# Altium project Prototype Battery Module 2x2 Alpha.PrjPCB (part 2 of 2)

## Sheet Host Comm.SchDoc: Host Communication
size B; Date: 12/18/2013; DrawnBy: David McCoy; Engineer: David McCoy (Cospan Design); DocumentNumber: 12; Revision: C; SheetNumber: 12; SheetTotal: 13
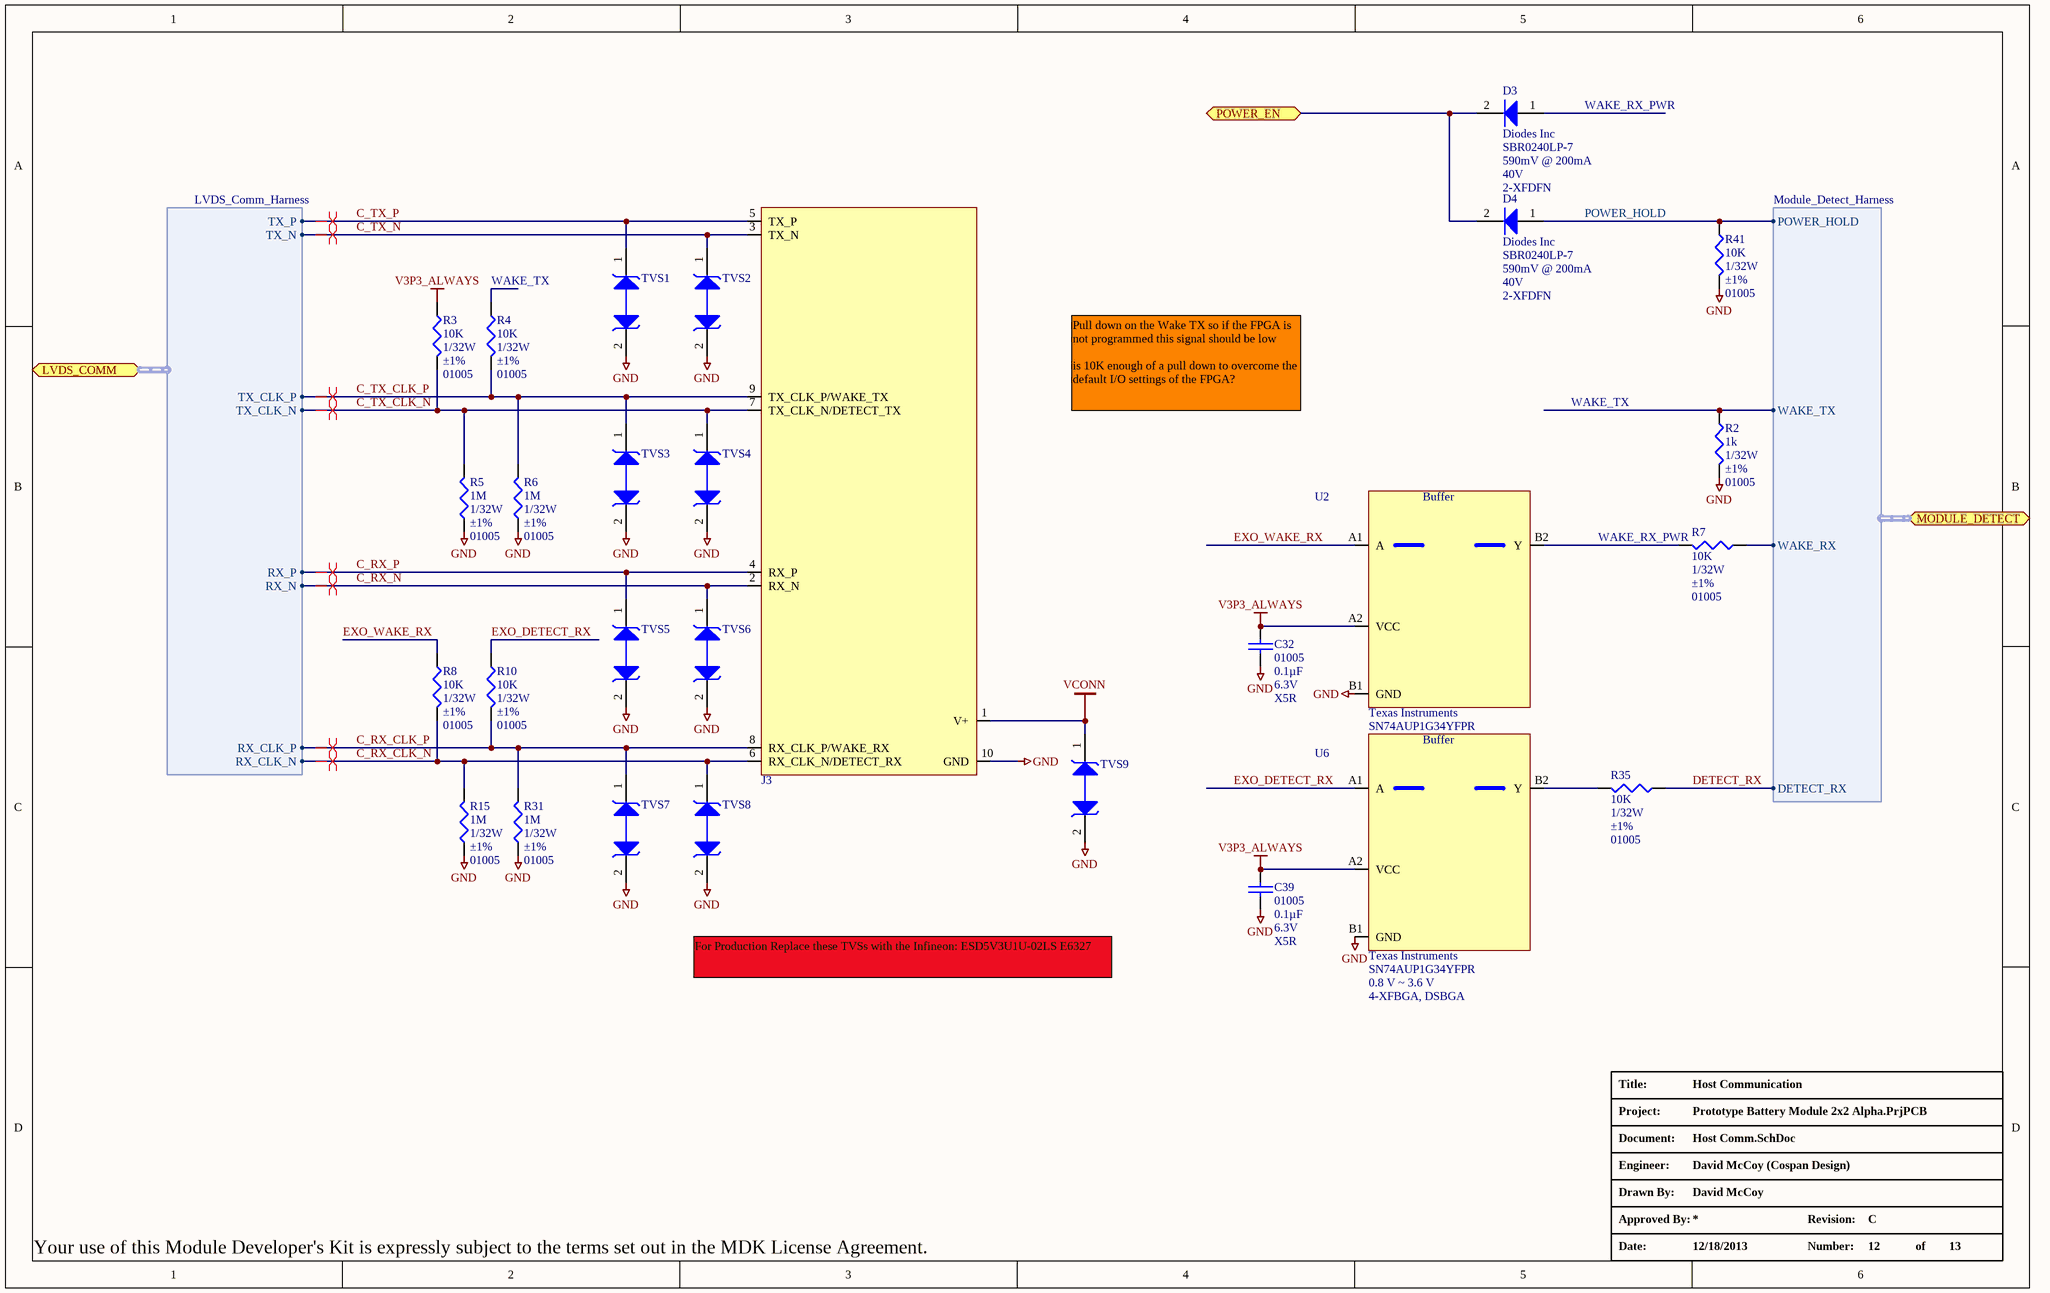
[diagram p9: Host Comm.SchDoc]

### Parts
C32  Package / Case: 01005  Capacitance: 0.1µF  Voltage - Rated: 6.3V  Temperature Coefficient: X5R  [C_01005]  (hidden comment: 0.1uF)
C39  Package / Case: 01005  Capacitance: 0.1µF  Voltage - Rated: 6.3V  Temperature Coefficient: X5R  [C_01005]  (hidden comment: 0.1uF)
D3  Manufacturer: Diodes Inc  Voltage - Forward (Vf) (Max) @ If: 590mV @ 200mA  Voltage - DC Reverse (Vr) (Max): 40V  [2-XFDFN]  (hidden comment: SBR0240LP-7)
D4  Manufacturer: Diodes Inc  Voltage - Forward (Vf) (Max) @ If: 590mV @ 200mA  Voltage - DC Reverse (Vr) (Max): 40V  [2-XFDFN]  (hidden comment: SBR0240LP-7)
J3  SPRING PIN  [10PIN SMD CONNECTOR]  (value not drawn)  (no BOM)
R2  Power (Watts): 1/32W  Tolerance: ±1%  Case: 01005  [R_01005]  (hidden comment: 1k)
R3  Power (Watts): 1/32W  Tolerance: ±1%  Case: 01005  [R_01005]  (hidden comment: 10K)
R4  Power (Watts): 1/32W  Tolerance: ±1%  Case: 01005  [R_01005]  (hidden comment: 10K)
R5  Resistance In Ohms: 1M  Power (Watts): 1/32W  Tolerance: ±1%  Case: 01005  [R_01005]  (hidden comment: 1M Ohms)
R6  Resistance In Ohms: 1M  Power (Watts): 1/32W  Tolerance: ±1%  Case: 01005  [R_01005]  (hidden comment: 1M Ohms)
R7  Power (Watts): 1/32W  Tolerance: ±1%  Case: 01005  [R_01005]  (hidden comment: 10K)
R8  Power (Watts): 1/32W  Tolerance: ±1%  Case: 01005  [R_01005]  (hidden comment: 10K)
R10  Power (Watts): 1/32W  Tolerance: ±1%  Case: 01005  [R_01005]  (hidden comment: 10K)
R15  Resistance In Ohms: 1M  Power (Watts): 1/32W  Tolerance: ±1%  Case: 01005  [R_01005]  (hidden comment: 1M Ohms)
R31  Resistance In Ohms: 1M  Power (Watts): 1/32W  Tolerance: ±1%  Case: 01005  [R_01005]  (hidden comment: 1M Ohms)
R35  Power (Watts): 1/32W  Tolerance: ±1%  Case: 01005  [R_01005]  (hidden comment: 10K)
R41  Power (Watts): 1/32W  Tolerance: ±1%  Case: 01005  [R_01005]  (hidden comment: 10K)
TVS1  TVS_ESDAVLC6-1BV2  [ST_MICRO_TVS]  (value not drawn)
TVS2  TVS_ESDAVLC6-1BV2  [ST_MICRO_TVS]  (value not drawn)
TVS3  TVS_ESDAVLC6-1BV2  [ST_MICRO_TVS]  (value not drawn)
TVS4  TVS_ESDAVLC6-1BV2  [ST_MICRO_TVS]  (value not drawn)
TVS5  TVS_ESDAVLC6-1BV2  [ST_MICRO_TVS]  (value not drawn)
TVS6  TVS_ESDAVLC6-1BV2  [ST_MICRO_TVS]  (value not drawn)
TVS7  TVS_ESDAVLC6-1BV2  [ST_MICRO_TVS]  (value not drawn)
TVS8  TVS_ESDAVLC6-1BV2  [ST_MICRO_TVS]  (value not drawn)
TVS9  TVS_ESDAVLC6-1BV2  [ST_MICRO_TVS]  (value not drawn)
U2  Manufacturer: Texas Instruments  Manufacturer Part Number: SN74AUP1G34YFPR  Voltage - Supply: 0.8 V ~ 3.6 V  Package / Case: 4-XFBGA, DSBGA  [DSBGA4_.4MM]  (hidden comment: Buffer)
U6  Manufacturer: Texas Instruments  Manufacturer Part Number: SN74AUP1G34YFPR  Voltage - Supply: 0.8 V ~ 3.6 V  Package / Case: 4-XFBGA, DSBGA  [DSBGA4_.4MM]  (hidden comment: Buffer)

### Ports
LVDS_COMM (harness LVDS_Comm_Harness), MODULE_DETECT (harness Module_Detect_Harness), POWER_EN

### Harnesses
Module_Detect_Harness: WAKE_TX, WAKE_RX, DETECT_RX, POWER_HOLD
LVDS_Comm_Harness: TX_P, TX_N, TX_CLK_P, TX_CLK_N, RX_P, RX_N, RX_CLK_P, RX_CLK_N

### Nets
GND: C32.1 C39.1 J3.10(GND) R2.1 R5.2 R6.2 R15.2 R31.2 R41.1 TVS1.2 TVS2.2 TVS3.2 TVS4.2 TVS5.2 TVS6.2 TVS7.2 TVS8.2 TVS9.2 U2.B1(GND) U6.B1(GND)
V3P3_ALWAYS: C32.2 C39.2 R3.2 U2.A2(VCC) U6.A2(VCC)
VCONN: J3.1(V+) TVS9.1
C_RX_CLK_N: J3.6(RX_CLK_N/DETECT_RX) R8.1 R15.1 TVS8.1 ; port LVDS_COMM.RX_CLK_N
C_RX_CLK_P: J3.8(RX_CLK_P/WAKE_RX) R10.1 R31.1 TVS7.1 ; port LVDS_COMM.RX_CLK_P
C_RX_N: J3.2(RX_N) TVS6.1 ; port LVDS_COMM.RX_N
C_RX_P: J3.4(RX_P) TVS5.1 ; port LVDS_COMM.RX_P
C_TX_CLK_N: J3.7(TX_CLK_N/DETECT_TX) R3.1 R5.1 TVS4.1 ; port LVDS_COMM.TX_CLK_N
C_TX_CLK_P: J3.9(TX_CLK_P/WAKE_TX) R4.1 R6.1 TVS3.1 ; port LVDS_COMM.TX_CLK_P
C_TX_N: J3.3(TX_N) TVS2.1 ; port LVDS_COMM.TX_N
C_TX_P: J3.5(TX_P) TVS1.1 ; port LVDS_COMM.TX_P
DETECT_RX: R35.2 ; port MODULE_DETECT.DETECT_RX
EXO_DETECT_RX: R10.2 U6.A1(A)
EXO_WAKE_RX: R8.2 U2.A1(A)
POWER_EN: D3.2(K) D4.2(K) ; port POWER_EN
POWER_HOLD: D4.1(A) R41.2 ; port MODULE_DETECT.POWER_HOLD
WAKE_RX: R7.2 ; port MODULE_DETECT.WAKE_RX
WAKE_RX_PWR: D3.1(A) R7.1 U2.B2(Y)
WAKE_TX: R2.2 R4.2 ; port MODULE_DETECT.WAKE_TX
NetR35_1: R35.1 U6.B2(Y)

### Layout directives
differential pair: C_RX_CLK_N, C_RX_CLK_P, C_RX_N, C_RX_P, C_TX_CLK_N, C_TX_CLK_P, C_TX_N, C_TX_P

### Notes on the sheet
- Pull down on the Wake TX so if the FPGA is not programmed this signal should be low
  is 10K enough of a pull down to overcome the default I/O settings of the FPGA?
- For Production Replace these TVSs with the Infineon: ESD5V3U1U-02LS E6327

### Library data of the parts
C32 C39 = C_01005_0.1uF: CAP CER 0.1UF 6.3V 20% X5R 01005; Manufacturer: TDK Corporation; Manufacturer Part Number: C0402X5R0J104M020BC
D3 D4 = D_SBR0240LP-7: DIODE SUP BARRIER 40V 0.25A 2DFN; Diode Type: Super Barrier; Current - Average Rectified (Io): 250mA; Speed: Fast Recovery =< 500ns, > 200mA (Io); Current - Reverse Leakage @ Vr: 10µA @ 40V; Thermal Resistance: 270°C/W Ja
J3 = J_TONKA_MODULE_CONNECTOR
R2 = R_01005_1k: RES 1K OHM 1/32W 1% 01005 SM; Manufacturer: Panasonic Electronic Components; Manufacturer Part Number: ERJ-XGNF1001Y; Temperature Coefficient: ±200ppm/°C
R3 R4 R7 R8 R10 R35 R41 = R_01005_10K: RES 10K OHM 1/32W 1% 01005; Manufacturer: Samsung Electro-Mechanics America, Inc; Manufacturer Part Number: RC0402F103CS; Temperature Coefficient: ±250ppm/°C
R5 R6 R15 R31 = R_01005_1M: RES 1M OHM 1/32W 1% 01005 SMD; Manufacturer: Yageo; Manufacturer Part Number: RC0100FR-071ML; Temperature Coefficient: ±250ppm/°C
TVS1-TVS9 = TVS_ESDAVLC6-1BV2: Single Line Bi Trans 8pF; Manufacturer: STMicroelectronics; Breakdown Voltage: 6 V; Capacitance: 7.5 pF; Clamping Voltage: 18 V; Channels: 1 Channel; Peak Pulse Power Dissipation: 45 W; Polarity: Bidirectional; Product Status: New Product
U2 U6 = U_SN74AUP1G34YFPR: IC BUFFER GATE SGL 4-DSBGA; Logic Type: Buffer/Line Driver, Non-Inverting; Number of Elements: 1; Current - Output High, Low: 4mA, 4mA

## Sheet Charger.SchDoc: Charger
size B; Date: 12/17/2013; DrawnBy: Ara Knaian; Engineer: Ara Knaian; DocumentNumber: 5; Revision: C; SheetNumber: 5; SheetTotal: 13
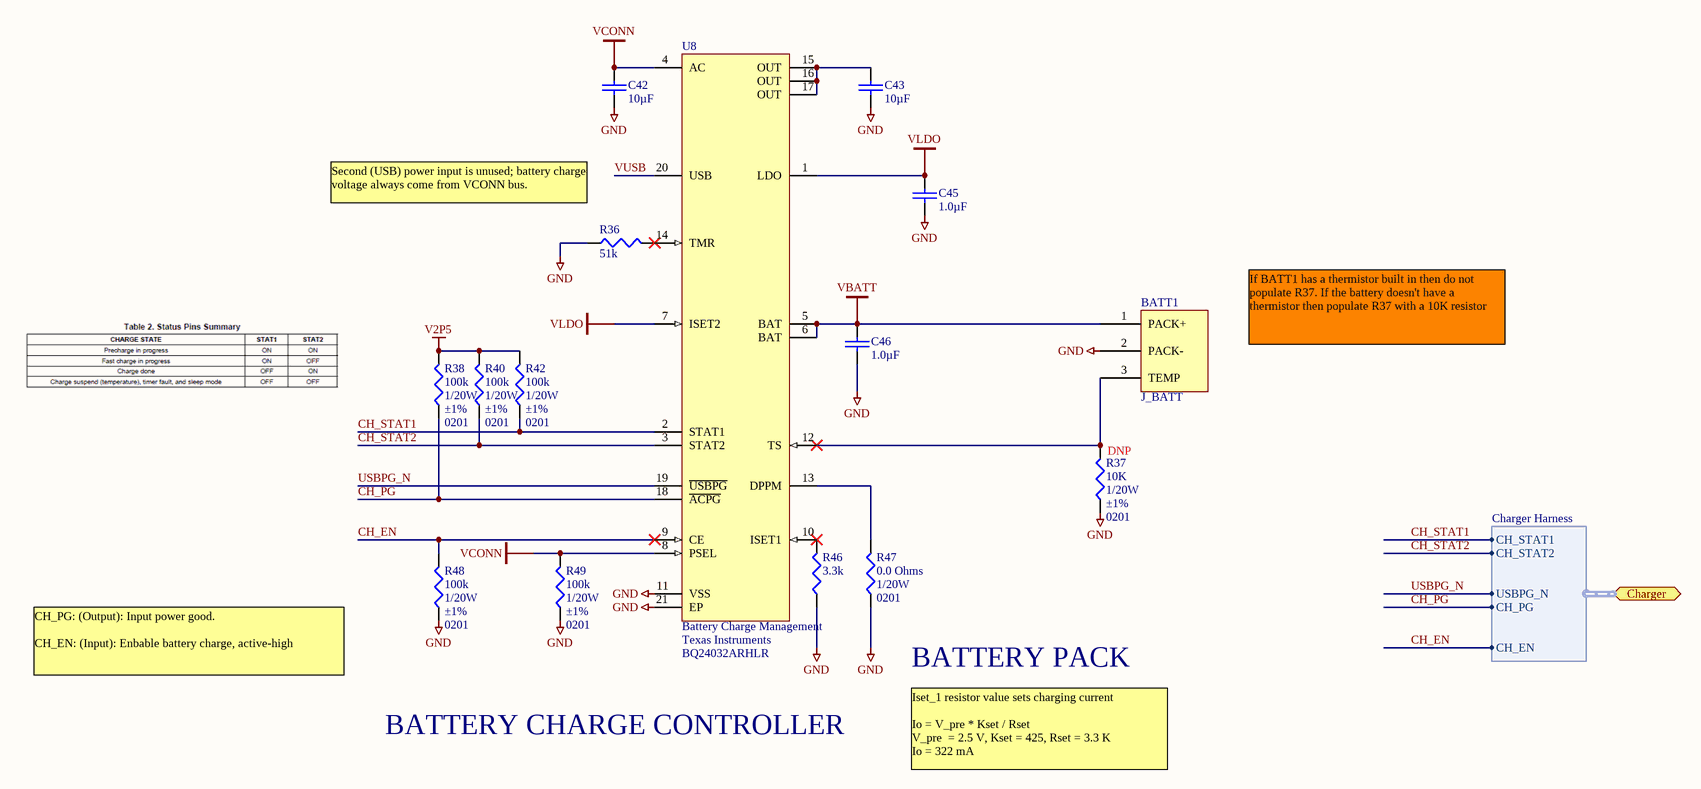
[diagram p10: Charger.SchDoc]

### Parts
BATT1  J_BATT  [1X3_PADS]  (no BOM)
C42  Capacitance: 10µF  [C_0402]  (hidden comment: C_0402_10uF)
C43  Capacitance: 10µF  [C_0402]  (hidden comment: C_0402_10uF)
C45  Capacitance: 1.0µF  [CAPC0201]  (hidden comment: 1uF)
C46  Capacitance: 1.0µF  [CAPC0201]  (hidden comment: 1uF)
R36  51K  [R_0201]
R37  Power (Watts): 1/20W  Tolerance: ±1%  Case: 0201  [R0201]  (hidden comment: 10K)
R38  Resistance In Ohms: 100k  Power (Watts): 1/20W  Tolerance: ±1%  Case: 0201  [R_0201]  (hidden comment: R_0201_100k)
R40  Resistance In Ohms: 100k  Power (Watts): 1/20W  Tolerance: ±1%  Case: 0201  [R_0201]  (hidden comment: R_0201_100k)
R42  Resistance In Ohms: 100k  Power (Watts): 1/20W  Tolerance: ±1%  Case: 0201  [R_0201]  (hidden comment: R_0201_100k)
R46  3.3K  [R_0201]
R47  Resistance In Ohms: 0.0 Ohms  Power (Watts): 1/20W  Case: 0201  [R_0201]  (hidden comment: 0 Ohms)
R48  Resistance In Ohms: 100k  Power (Watts): 1/20W  Tolerance: ±1%  Case: 0201  [R_0201]  (hidden comment: R_0201_100k)
R49  Resistance In Ohms: 100k  Power (Watts): 1/20W  Tolerance: ±1%  Case: 0201  [R_0201]  (hidden comment: R_0201_100k)
U8  SubFamily: Battery Charge Management  Manufacturer: Texas Instruments  Manufacturer Part Number: BQ24032ARHLR  [RHL20-3050X2050TP]  (hidden comment: U_BQ24032ARHLR)

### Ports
Charger (harness Charger Harness)

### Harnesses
Charger Harness: CH_STAT1, CH_STAT2, USBPG_N, CH_PG, CH_EN

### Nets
GND: BATT1.2(PACK-) C42.1 C43.1 C45.1 C46.1 R36.2 R37.2 R46.2 R47.2 R48.2 R49.2 U8.11(VSS) U8.21(EP)
V2P5: R38.1 R40.1 R42.1
VBATT: BATT1.1(PACK+) C46.2 U8.5(BAT) U8.6(BAT)
VCONN: C42.2 R49.1 U8.4(AC) U8.8(PSEL)
VLDO: C45.2 U8.1(LDO) U8.7(ISET2)
CH_EN: R48.1 U8.9(CE) ; port Charger.CH_EN
CH_PG: R38.2 U8.18(~{ACPG}) ; port Charger.CH_PG
CH_STAT1: R42.2 U8.2(STAT1) ; port Charger.CH_STAT1
CH_STAT2: R40.2 U8.3(STAT2) ; port Charger.CH_STAT2
USBPG_N: U8.19(~{USBPG}) ; port Charger.USBPG_N
VUSB: U8.20(USB)
NetBATT1_3: BATT1.3(TEMP) R37.1 U8.12(TS)
NetC43_2: C43.2 U8.15(OUT) U8.16(OUT) U8.17(OUT)
NetR36_1: R36.1 U8.14(TMR)
NetR46_1: R46.1 U8.10(ISET1)
NetR47_1: R47.1 U8.13(DPPM)

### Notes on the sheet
- (near R36) Second (USB) power input is unused; battery charge voltage always come from VCONN bus.
- If BATT1 has a thermistor built in then do not populate R37. If the battery doesn't have a thermistor then populate R37 with a 10K resistor
- CH_PG: (Output): Input power good.
  CH_EN: (Input): Enbable battery charge, active-high
- BATTERY PACK
- BATTERY CHARGE CONTROLLER
- Iset_1 resistor value sets charging current
  Io = V_pre * Kset / Rset
  V_pre  = 2.5 V, Kset = 425, Rset = 3.3 K
  Io = 322 mA

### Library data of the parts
C42 C43 = C_0402_10uF: 10uF; Manufacturer: Samsung Electro-Mechanics America, Inc; Manufacturer Part Number: CL05A106MQ5NUNC; Voltage - Rated: 6.3V; Tolerance: ±20%; Temperature Coefficient: X5R
C45 C46 = C_0201_1UF: Manufacturer: TDK Corporation; Manufacturer Part Number: C0603X5R0J105M030BC; Voltage - Rated: 6.3V; Tolerance: ±20%; Temperature Coefficient: X5R
R36 = R_0201_51K: Manufacturer: Rohm Semiconductor; Manufacturer Part Number: MCR006YRTF5102; Tolerance: ±1%; Power (Watts): 0.05W, 1/20W; Temperature Coefficient: ±250ppm/°C
R37 = R_0201_10K: RES 10K OHM 1/20W 1% 0201 SMD; Manufacturer: Rohm Semiconductor; Manufacturer Part Number: MCR006YRTF1002; Temperature Coefficient: ±250ppm/°C
R38 R40 R42 R48 R49 = R_0201_100k: Manufacturer: Rohm Semiconductor; Manufacturer Part Number: MCR006YRTF1003; Temperature Coefficient: ±250ppm/°C
R46 = R_0201_3.3K: Manufacturer: Rohm Semiconductor; Manufacturer Part Number: MCR006YRTF3301; Tolerance: ±1%; Power (Watts): 0.05W, 1/20W; Temperature Coefficient: ±250ppm/°C
R47 = R_0201_0.0: Manufacturer: Panasonic Electronic Components; Manufacturer Part Number: ERJ-1GE0R00C; Resistance (Ohms): 0.0; Tolerance: Jumper
U8 = U_BQ24032ARHLR: Dual Input Li-Ion Charger with Dynamic Power Path, Output regulated to 4.4 V, Vbat 4.2 V, 4.3 V, -40 to 85 degC, 20-pin QFN (RHL), Green (RoHS & no Sb/Br); Lead Acid: N; Li-Ion: Y; Vin(Min)(V): 4.3; Function: Charge Management; Battery Chemistry: Li-Ion, Li-Pol; Voltage - Supply: 4.35 V ~ 16 V

## Sheet Ideal Diode.SchDoc: Ideal Diode
size B; Date: 12/17/2013; DrawnBy: Ara Knaian; Engineer: Ara Knaian; DocumentNumber: 4; Revision: C; SheetNumber: 4; SheetTotal: 13
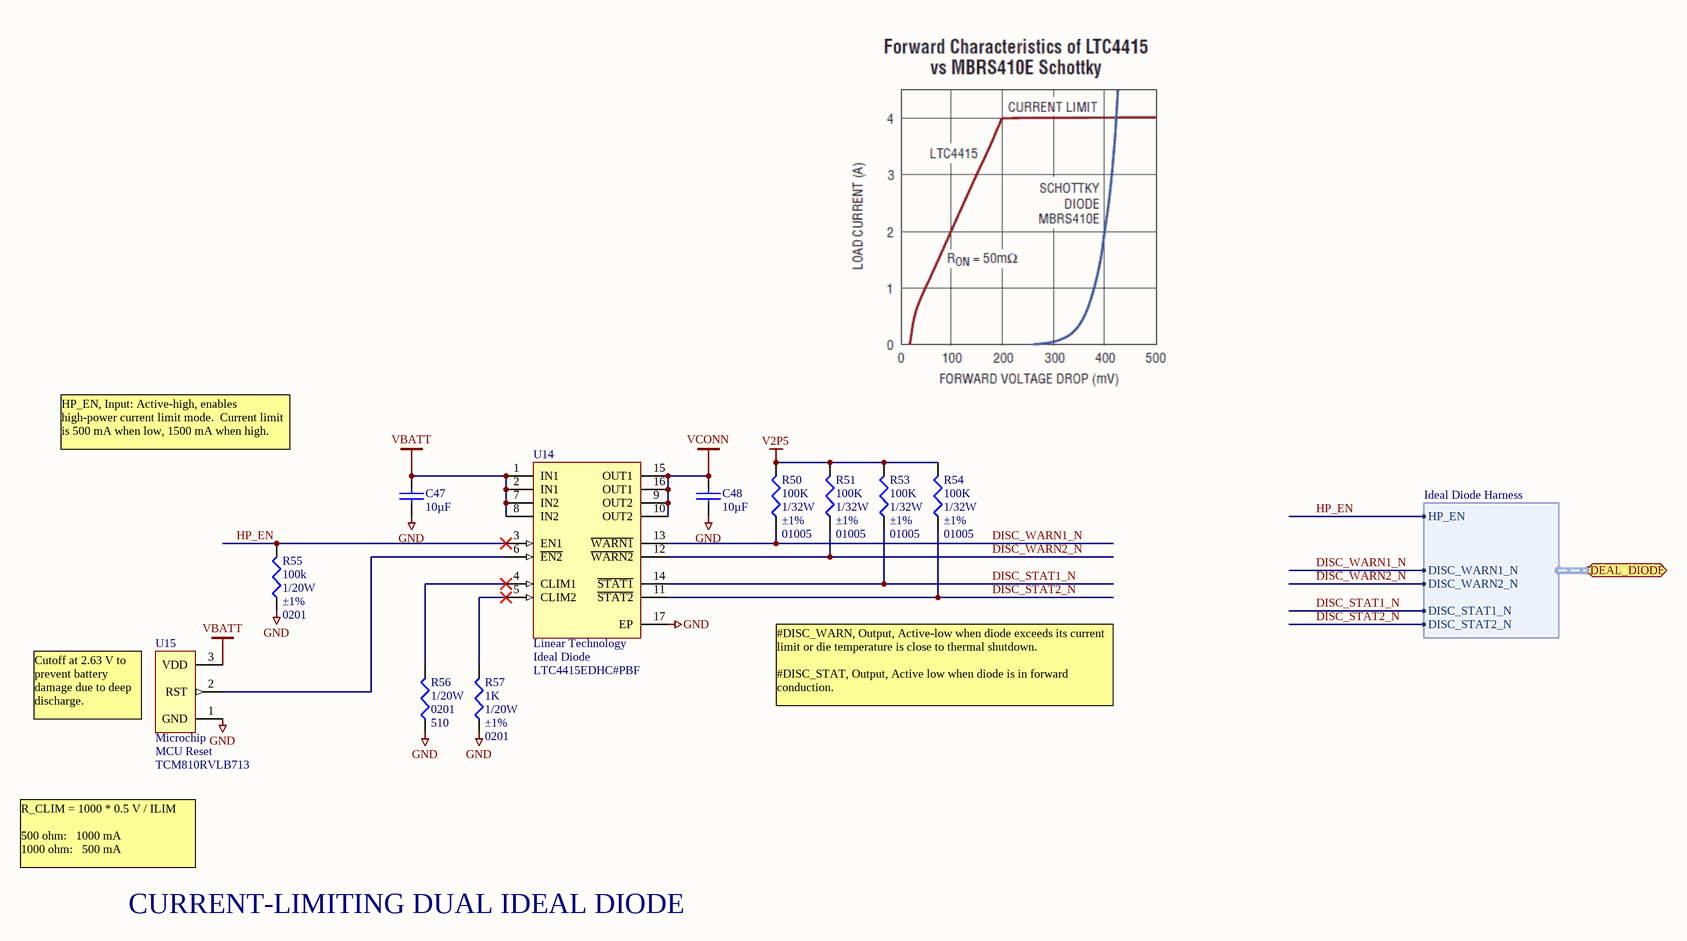
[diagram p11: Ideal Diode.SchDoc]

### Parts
C47  Capacitance: 10µF  [C_0402]  (hidden comment: C_0402_10uF)
C48  Capacitance: 10µF  [C_0402]  (hidden comment: C_0402_10uF)
R50  Power (Watts): 1/32W  Tolerance: ±1%  Case: 01005  [R_01005]  (hidden comment: 100K)
R51  Power (Watts): 1/32W  Tolerance: ±1%  Case: 01005  [R_01005]  (hidden comment: 100K)
R53  Power (Watts): 1/32W  Tolerance: ±1%  Case: 01005  [R_01005]  (hidden comment: 100K)
R54  Power (Watts): 1/32W  Tolerance: ±1%  Case: 01005  [R_01005]  (hidden comment: 100K)
R55  Resistance In Ohms: 100k  Power (Watts): 1/20W  Tolerance: ±1%  Case: 0201  [R_0201]  (hidden comment: R_0201_100k)
R56  Power (Watts): 1/20W  Package / Case: 0201  Resistance (Ohms): 510  [R_0201]  (hidden comment: R_0201_510)
R57  Power (Watts): 1/20W  Tolerance: ±1%  Case: 0201  [R_0201]  (hidden comment: 1K)
U14  Manufacturer: Linear Technology  NOTE: Ideal Diode  Manufacturer Part Number: LTC4415EDHC#PBF  [LT-DHC-16_A_V]  (hidden comment: U_LTC4415EDHC#PBF)
U15  Manufacturer: Microchip  NOTE: MCU Reset  [SC70-LB3_N]  (hidden comment: TCM810RVLB713)

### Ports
IDEAL_DIODE (harness Ideal Diode Harness)

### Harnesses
Ideal Diode Harness: HP_EN, DISC_WARN1_N, DISC_WARN2_N, DISC_STAT1_N, DISC_STAT2_N

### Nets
GND: C47.1 C48.1 R55.2 R56.2 R57.2 U14.17(EP) U15.1(GND)
V2P5: R50.1 R51.1 R53.1 R54.1
VBATT: C47.2 U14.1(IN1) U14.2(IN1) U14.7(IN2) U14.8(IN2) U15.3(VDD)
VCONN: C48.2 U14.9(OUT2) U14.10(OUT2) U14.15(OUT1) U14.16(OUT1)
DISC_STAT1_N: R53.2 U14.14(~{STAT1}) ; port IDEAL_DIODE.DISC_STAT1_N
DISC_STAT2_N: R54.2 U14.11(~{STAT2}) ; port IDEAL_DIODE.DISC_STAT2_N
DISC_WARN1_N: R50.2 U14.13(~{WARN1}) ; port IDEAL_DIODE.DISC_WARN1_N
DISC_WARN2_N: R51.2 U14.12(~{WARN2}) ; port IDEAL_DIODE.DISC_WARN2_N
HP_EN: R55.1 U14.3(EN1) ; port IDEAL_DIODE.HP_EN
NetR56_1: R56.1 U14.4(CLIM1)
NetR57_1: R57.1 U14.5(CLIM2)
NetU14_6: U14.6(~{EN2}) U15.2(RST)

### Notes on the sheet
- HP_EN, Input: Active-high, enables high-power current limit mode.  Current limit is 500 mA when low, 1500 mA when high.
- Cutoff at 2.63 V to prevent battery damage due to deep discharge.
- #DISC_WARN, Output, Active-low when diode exceeds its current limit or die temperature is close to thermal shutdown.
  #DISC_STAT, Output, Active low when diode is in forward conduction.
- R_CLIM = 1000 * 0.5 V / ILIM
  500 ohm:   1000 mA
  1000 ohm:   500 mA
- CURRENT-LIMITING DUAL IDEAL DIODE

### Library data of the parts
C47 C48 = C_0402_10uF: as C42 on sheet Charger
R50 R51 R53 R54 = R_01005_100K: RES 100K OHM 1/32W 1% 01005 SMD; Manufacturer: Yageo; Manufacturer Part Number: RC0100FR-07100KL; Temperature Coefficient: ±250ppm/°C
R55 = R_0201_100k: as R38 on sheet Charger
R56 = R_0201_510: 510 Ohm; Manufacturer: Rohm Semiconductor; Manufacturer Part Number: MCR006YRTF5100; Tolerance: ±1%; Temperature Coefficient: ±250ppm/°C
R57 = R_0201_1K: RES 1K OHM 1/20W 1% 0201 SMD; Manufacturer: Rohm Semiconductor; Manufacturer Part Number: MCR006YRTF1001; Temperature Coefficient: ±250ppm/°C
U14 = U_LTC4415EDHC#PBF: IC OR CTRLR SRC SELECT 16DFN; Ideal Diode: Dual, Internal, P-Channel; FET Type: P-Channel; Ratio - Input:Output: 2:2; Internal Switch(s): Yes; Current - Output (Max): 4A; Current - Supply: 44µA; Voltage - Supply: 1.7 V ~ 5.5 V
U15 = U_TCM810RVLB713: IC RESET MONITOR 2.63V SC70-3; Number of Voltages Monitored: 1; Output: Push-Pull, Totem Pole; Reset: Active High; Reset Timeout: 140 ms Minimum

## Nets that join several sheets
GND: Block Diagram (S1.S T1.1), FPGA Banks (25 pins), FPGA Config (16 pins), FPGA Power (148 pins), Power (20 pins), EPM (30 pins), Host Comm (20 pins), Charger (13 pins), Ideal Diode (7 pins)
V1P2: FPGA Power (38 pins), Power (C40.2 C41.2 U11.A1)
V2P5: FPGA Banks (7 pins), Power (C82.2 L1.2 U12.C3), Charger (R38.1 R40.1 R42.1), Ideal Diode (R50.1 R51.1 R53.1 R54.1)
V3P3: Block Diagram (T1.2), FPGA Banks (38 pins), FPGA Config (17 pins), FPGA Power (11 pins), Power (C95.2 U13.A1), EPM (C9.2 L2.1 U4.4)
V3P3_ALWAYS: Power (8 pins), Host Comm (5 pins)
VBATT: Charger (BATT1.1 C46.2 U8.5 U8.6), Ideal Diode (6 pins)
VCONN: Power (7 pins), Host Comm (J3.1 TVS9.1), Charger (C42.2 R49.1 U8.4 U8.8), Ideal Diode (5 pins)
C_RX_CLK_N: FPGA Banks (C90.1), Host Comm (J3.6 R8.1 R15.1 TVS8.1)
C_RX_CLK_P: FPGA Banks (C89.1), Host Comm (J3.8 R10.1 R31.1 TVS7.1)
C_RX_N: FPGA Banks (C88.1), Host Comm (J3.2 TVS6.1)
C_RX_P: FPGA Banks (C87.1), Host Comm (J3.4 TVS5.1)
C_TX_CLK_N: FPGA Banks (C86.1), Host Comm (J3.7 R3.1 R5.1 TVS4.1)
C_TX_CLK_P: FPGA Banks (C85.1), Host Comm (J3.9 R4.1 R6.1 TVS3.1)
C_TX_N: FPGA Banks (C84.1), Host Comm (J3.3 TVS2.1)
C_TX_P: FPGA Banks (C83.1), Host Comm (J3.5 TVS1.1)
CH_EN: FPGA Banks (U3.M1), Charger (R48.1 U8.9)
CH_PG: FPGA Banks (U3.M2), Charger (R38.2 U8.18)
CH_STAT1: FPGA Banks (U3.K2), Charger (R42.2 U8.2)
CH_STAT2: FPGA Banks (U3.L2), Charger (R40.2 U8.3)
DETECT_RX: FPGA Banks (U3.B13), Host Comm (R35.2)
DISC_STAT1_N: FPGA Banks (U3.G3), Ideal Diode (R53.2 U14.14)
DISC_STAT2_N: FPGA Banks (U3.N2), Ideal Diode (R54.2 U14.11)
DISC_WARN1_N: FPGA Banks (U3.N3), Ideal Diode (R50.2 U14.13)
DISC_WARN2_N: FPGA Banks (U3.G2), Ideal Diode (R51.2 U14.12)
EPM_HBA_N: FPGA Banks (U3.R18), EPM (Q3.1)
EPM_HBA_P: FPGA Banks (U3.V18), EPM (Q2.1 R59.1)
EPM_HBB_N: FPGA Banks (U3.T17), EPM (Q8.1)
EPM_HBB_P: FPGA Banks (U3.R17), EPM (Q7.1 R60.1)
EPM_HBC_N: FPGA Banks (U3.R19), EPM (Q11.1)
EPM_HBC_P: FPGA Banks (U3.T18), EPM (Q10.1 R61.1)
EPM_HBD_N: FPGA Banks (U3.P19), EPM (Q12.1)
EPM_HBD_P: FPGA Banks (U3.P17), EPM (Q9.1 R62.1)
EPM_REG_EN: FPGA Banks (U3.V19), EPM (R9.1 U4.6)
HP_EN: FPGA Banks (U3.M3), Ideal Diode (R55.1 U14.3)
POWER_EN: Power (R1.1 U11.B2 U12.C1 U13.B2), Host Comm (D3.2 D4.2)
POWER_HOLD: FPGA Banks (U3.C13), Host Comm (D4.1 R41.2)
USBPG_N: FPGA Banks (U3.L1), Charger (U8.19)
WAKE_RX: FPGA Banks (U3.C12), Host Comm (R7.2)
WAKE_TX: FPGA Banks (U3.A11), Host Comm (R2.2 R4.2)

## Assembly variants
Production: not fitted R37 TVS1 TVS2 TVS3 TVS4 TVS5 TVS6 TVS7 TVS8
